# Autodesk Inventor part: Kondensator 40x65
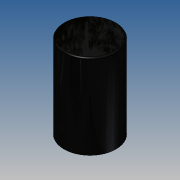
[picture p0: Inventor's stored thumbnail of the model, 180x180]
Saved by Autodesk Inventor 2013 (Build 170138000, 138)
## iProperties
Created: 2012-08
Part Number: Kondensator 40x65
Material: PC/ABS-Kunststoff
Document SubType Name: Modeling
Designer: rYan
Density: 1.493 g/cm^3
Mass: 121.967 g
Surface Area: 107.024 cm^2
Volume: 81.6924 cm^3
Author: rYan
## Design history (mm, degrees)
sketch "Skizze1"
  geometry: C1 r 20 at (0, 0); 1 further point
  constraints: 1 centre point, 1 coincident
  dimensions: "d0" = 40 diameter of C1
extrude "Extrusion1" new body sketch "Skizze1" distance "d1" = 65; taper "d2" = 0 deg
fillet "Rundung1" dims "d3" = 1
sketch "Skizze2"
  geometry: L1 (-28, 0)-(28, 0) reference; L2 (0, -28)-(0, 28) reference; C1 r 1 at (-5, 0); C2 r 1 at (5, 0); 2 further points
  constraints: 2 centre point, 2 coincident, 2 point on line, 1 symmetric about line, 1 other
  dimensions: "d4" = 10 distance of point (5, 0) point (-5, 0); "d5" = 2 diameter of C1
extrude "Extrusion2" join sketch "Skizze2" distance "d6" = 6; taper "d7" = 0 deg
workplane "Arbeitsebene1"
node "Volumenkörper1"
other parameters: "d8" = 0
